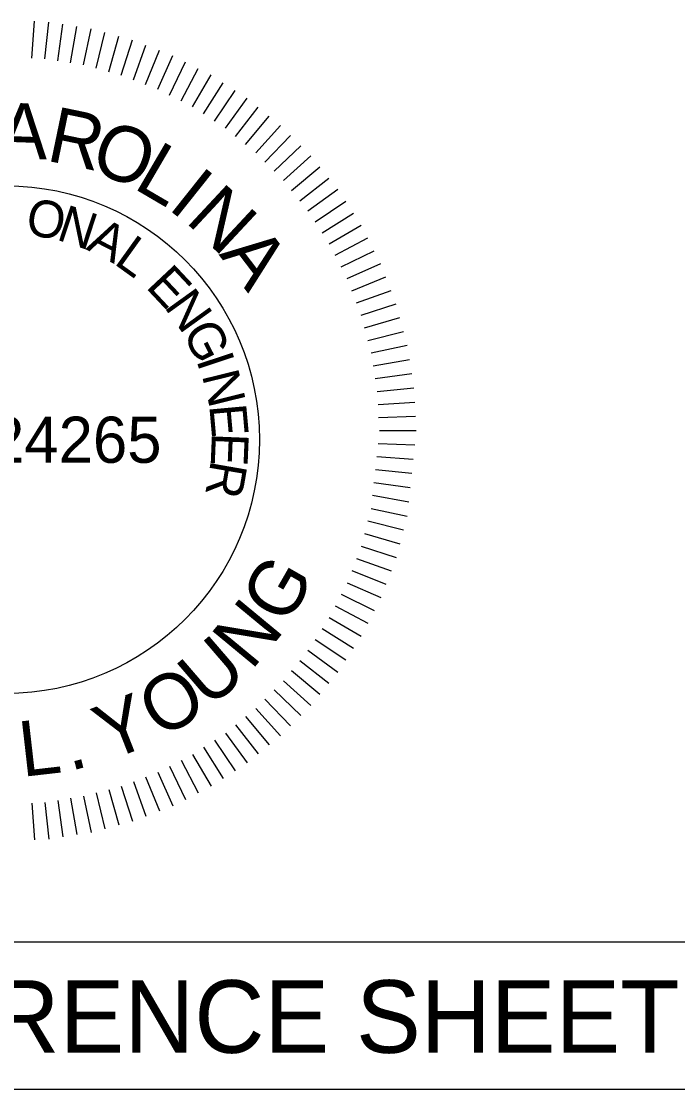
# Model space of a CAD drawing. Extents: x 1964850 to 1967424, y 1116563 to 1122204.
# Drawn here: x 1966494 to 1966557.3, y 1121679.1 to 1121782.1 of the extents above; entities that cross this region are included whole.
import ezdxf

# ---------------------------------------------------------------- set-up
doc = ezdxf.new("R2010")
doc.units = 0
doc.layers.add('RD_Sketch1', color=7, linetype='Continuous')
doc.layers.add('RD_TX_PEShield', color=7, linetype='Continuous')

msp = doc.modelspace()

# ---------------------------------------------------------------- linework, layer by layer
at = {"layer": 'RD_Sketch1'}
msp.add_lwpolyline([(1966266.73, 1121693.39), (1966567.16, 1121693.39), (1966567.16, 1121679.13), (1966266.73, 1121679.13)], close=True, dxfattribs=at)
at = {"layer": 'RD_TX_PEShield'}
for p, q in [((1966494.98, 1121778.59), (1966495.22, 1121782.14)), ((1966494.98, 1121778.59), (1966495.22, 1121782.14)), ((1966496.23, 1121778.52), (1966496.6, 1121782.06)), ((1966496.23, 1121778.52), (1966496.6, 1121782.06)), ((1966497.47, 1121778.33), (1966497.97, 1121781.85)), ((1966497.47, 1121778.33), (1966497.97, 1121781.85)), ((1966498.72, 1121778.13), (1966499.33, 1121781.63)), ((1966498.72, 1121778.13), (1966499.33, 1121781.63)), ((1966499.96, 1121777.93), (1966500.7, 1121781.41)), ((1966499.96, 1121777.93), (1966500.7, 1121781.41)), ((1966499.96, 1121777.93), (1966500.7, 1121781.41)), ((1966501.17, 1121777.61), (1966502.03, 1121781.06)), ((1966501.17, 1121777.61), (1966502.03, 1121781.06)), ((1966501.17, 1121777.61), (1966502.03, 1121781.06)), ((1966502.39, 1121777.28), (1966503.37, 1121780.7)), ((1966502.39, 1121777.28), (1966503.37, 1121780.7)), ((1966502.39, 1121777.28), (1966503.37, 1121780.7)), ((1966503.6, 1121776.96), (1966504.7, 1121780.34)), ((1966503.6, 1121776.96), (1966504.7, 1121780.34)), ((1966503.6, 1121776.96), (1966504.7, 1121780.34)), ((1966504.78, 1121776.51), (1966505.99, 1121779.85)), ((1966504.78, 1121776.51), (1966505.99, 1121779.85)), ((1966504.78, 1121776.51), (1966505.99, 1121779.85)), ((1966505.95, 1121776.05), (1966507.28, 1121779.35)), ((1966505.95, 1121776.05), (1966507.28, 1121779.35)), ((1966505.95, 1121776.05), (1966507.28, 1121779.35)), ((1966507.12, 1121775.6), (1966508.57, 1121778.86)), ((1966507.12, 1121775.6), (1966508.57, 1121778.86)), ((1966507.12, 1121775.6), (1966508.57, 1121778.86)), ((1966508.25, 1121775.03), (1966509.8, 1121778.23)), ((1966508.25, 1121775.03), (1966509.8, 1121778.23)), ((1966508.25, 1121775.03), (1966509.8, 1121778.23)), ((1966509.37, 1121774.46), (1966511.03, 1121777.6)), ((1966509.37, 1121774.46), (1966511.03, 1121777.6)), ((1966509.37, 1121774.46), (1966511.03, 1121777.6)), ((1966510.49, 1121773.89), (1966512.27, 1121776.97)), ((1966510.49, 1121773.89), (1966512.27, 1121776.97)), ((1966510.49, 1121773.89), (1966512.27, 1121776.97)), ((1966511.54, 1121773.21), (1966513.43, 1121776.22)), ((1966511.54, 1121773.21), (1966513.43, 1121776.22)), ((1966511.54, 1121773.21), (1966513.43, 1121776.22)), ((1966512.6, 1121772.52), (1966514.58, 1121775.47)), ((1966512.6, 1121772.52), (1966514.58, 1121775.47)), ((1966512.6, 1121772.52), (1966514.58, 1121775.47)), ((1966513.65, 1121771.84), (1966515.74, 1121774.72)), ((1966513.65, 1121771.84), (1966515.74, 1121774.72)), ((1966513.65, 1121771.84), (1966515.74, 1121774.72)), ((1966514.63, 1121771.04), (1966516.82, 1121773.85)), ((1966514.63, 1121771.04), (1966516.82, 1121773.85)), ((1966514.63, 1121771.04), (1966516.82, 1121773.85)), ((1966515.6, 1121770.25), (1966517.89, 1121772.98)), ((1966515.6, 1121770.25), (1966517.89, 1121772.98)), ((1966515.6, 1121770.25), (1966517.89, 1121772.98)), ((1966516.58, 1121769.46), (1966518.96, 1121772.11)), ((1966516.58, 1121769.46), (1966518.96, 1121772.11)), ((1966516.58, 1121769.46), (1966518.96, 1121772.11)), ((1966517.47, 1121768.57), (1966519.94, 1121771.13)), ((1966517.47, 1121768.57), (1966519.94, 1121771.13)), ((1966517.47, 1121768.57), (1966519.94, 1121771.13)), ((1966518.36, 1121767.68), (1966520.92, 1121770.15)), ((1966518.36, 1121767.68), (1966520.92, 1121770.15)), ((1966518.36, 1121767.68), (1966520.92, 1121770.15)), ((1966519.25, 1121766.79), (1966521.9, 1121769.18)), ((1966519.25, 1121766.79), (1966521.9, 1121769.18)), ((1966519.25, 1121766.79), (1966521.9, 1121769.18)), ((1966520.04, 1121765.82), (1966522.77, 1121768.1)), ((1966520.04, 1121765.82), (1966522.77, 1121768.1)), ((1966520.04, 1121765.82), (1966522.77, 1121768.1)), ((1966520.83, 1121764.84), (1966523.64, 1121767.03)), ((1966520.83, 1121764.84), (1966523.64, 1121767.03)), ((1966520.83, 1121764.84), (1966523.64, 1121767.03)), ((1966521.62, 1121763.86), (1966524.5, 1121765.95)), ((1966521.62, 1121763.86), (1966524.5, 1121765.95)), ((1966521.62, 1121763.86), (1966524.5, 1121765.95)), ((1966522.31, 1121762.81), (1966525.26, 1121764.79)), ((1966522.31, 1121762.81), (1966525.26, 1121764.79)), ((1966522.31, 1121762.81), (1966525.26, 1121764.79)), ((1966522.99, 1121761.75), (1966526.01, 1121763.64)), ((1966522.99, 1121761.75), (1966526.01, 1121763.64)), ((1966522.99, 1121761.75), (1966526.01, 1121763.64)), ((1966523.68, 1121760.7), (1966526.76, 1121762.48)), ((1966523.68, 1121760.7), (1966526.76, 1121762.48)), ((1966523.68, 1121760.7), (1966526.76, 1121762.48)), ((1966524.25, 1121759.58), (1966527.39, 1121761.25)), ((1966524.25, 1121759.58), (1966527.39, 1121761.25)), ((1966524.25, 1121759.58), (1966527.39, 1121761.25)), ((1966524.82, 1121758.46), (1966528.02, 1121760.02)), ((1966524.82, 1121758.46), (1966528.02, 1121760.02)), ((1966524.82, 1121758.46), (1966528.02, 1121760.02)), ((1966525.39, 1121757.34), (1966528.64, 1121758.78)), ((1966525.39, 1121757.34), (1966528.64, 1121758.78)), ((1966525.39, 1121757.34), (1966528.64, 1121758.78)), ((1966525.84, 1121756.16), (1966529.14, 1121757.49)), ((1966525.84, 1121756.16), (1966529.14, 1121757.49)), ((1966525.84, 1121756.16), (1966529.14, 1121757.49)), ((1966526.29, 1121754.99), (1966529.64, 1121756.2)), ((1966526.29, 1121754.99), (1966529.64, 1121756.2)), ((1966526.29, 1121754.99), (1966529.64, 1121756.2)), ((1966526.74, 1121753.81), (1966530.13, 1121754.91)), ((1966526.74, 1121753.81), (1966530.13, 1121754.91)), ((1966526.74, 1121753.81), (1966530.13, 1121754.91)), ((1966527.07, 1121752.6), (1966530.49, 1121753.58)), ((1966527.07, 1121752.6), (1966530.49, 1121753.58)), ((1966527.07, 1121752.6), (1966530.49, 1121753.58)), ((1966527.4, 1121751.38), (1966530.85, 1121752.24)), ((1966527.4, 1121751.38), (1966530.85, 1121752.24)), ((1966527.4, 1121751.38), (1966530.85, 1121752.24)), ((1966527.72, 1121750.17), (1966531.2, 1121750.91)), ((1966527.72, 1121750.17), (1966531.2, 1121750.91)), ((1966527.72, 1121750.17), (1966531.2, 1121750.91)), ((1966527.92, 1121748.93), (1966531.42, 1121749.54)), ((1966527.92, 1121748.93), (1966531.42, 1121749.54)), ((1966527.92, 1121748.93), (1966531.42, 1121749.54)), ((1966528.11, 1121747.69), (1966531.64, 1121748.18)), ((1966528.11, 1121747.69), (1966531.64, 1121748.18)), ((1966528.11, 1121747.69), (1966531.64, 1121748.18)), ((1966528.31, 1121746.44), (1966531.85, 1121746.81)), ((1966528.31, 1121746.44), (1966531.85, 1121746.81)), ((1966528.31, 1121746.44), (1966531.85, 1121746.81)), ((1966528.38, 1121745.19), (1966531.92, 1121745.43)), ((1966528.38, 1121745.19), (1966531.92, 1121745.43)), ((1966528.38, 1121745.19), (1966531.92, 1121745.43)), ((1966528.44, 1121743.93), (1966532, 1121744.06)), ((1966528.44, 1121743.93), (1966532, 1121744.06)), ((1966528.44, 1121743.93), (1966532, 1121744.06)), ((1966528.51, 1121742.68), (1966532.07, 1121742.68)), ((1966528.51, 1121742.68), (1966532.07, 1121742.68)), ((1966528.51, 1121742.68), (1966532.07, 1121742.68)), ((1966528.38, 1121741.42), (1966531.92, 1121741.3)), ((1966528.38, 1121741.42), (1966531.92, 1121741.3)), ((1966528.25, 1121740.17), (1966531.78, 1121739.93)), ((1966528.25, 1121740.17), (1966531.78, 1121739.93)), ((1966528.12, 1121738.93), (1966531.64, 1121738.56)), ((1966528.12, 1121738.93), (1966531.64, 1121738.56)), ((1966527.98, 1121737.68), (1966531.49, 1121737.19)), ((1966527.98, 1121737.68), (1966531.49, 1121737.19)), ((1966527.85, 1121736.44), (1966531.35, 1121735.82)), ((1966527.85, 1121736.44), (1966531.35, 1121735.82)), ((1966527.72, 1121735.18), (1966531.2, 1121734.44)), ((1966527.72, 1121735.18), (1966531.2, 1121734.44)), ((1966527.4, 1121733.97), (1966530.85, 1121733.11)), ((1966527.4, 1121733.97), (1966530.85, 1121733.11)), ((1966527.07, 1121732.75), (1966530.49, 1121731.77)), ((1966527.07, 1121732.75), (1966530.49, 1121731.77)), ((1966526.74, 1121731.54), (1966530.13, 1121730.44)), ((1966526.74, 1121731.54), (1966530.13, 1121730.44)), ((1966526.29, 1121730.36), (1966529.64, 1121729.15)), ((1966526.29, 1121730.36), (1966529.64, 1121729.15)), ((1966525.84, 1121729.19), (1966529.14, 1121727.86)), ((1966525.84, 1121729.19), (1966529.14, 1121727.86)), ((1966525.39, 1121728.01), (1966528.64, 1121726.57)), ((1966525.39, 1121728.01), (1966528.64, 1121726.57)), ((1966524.82, 1121726.89), (1966528.02, 1121725.33)), ((1966524.82, 1121726.89), (1966528.02, 1121725.33)), ((1966524.25, 1121725.77), (1966527.39, 1121724.1)), ((1966524.25, 1121725.77), (1966527.39, 1121724.1)), ((1966523.68, 1121724.65), (1966526.76, 1121722.87)), ((1966523.68, 1121724.65), (1966526.76, 1121722.87)), ((1966522.99, 1121723.6), (1966526.01, 1121721.71)), ((1966522.99, 1121723.6), (1966526.01, 1121721.71)), ((1966522.31, 1121722.54), (1966525.26, 1121720.56)), ((1966522.31, 1121722.54), (1966525.26, 1121720.56)), ((1966521.62, 1121721.49), (1966524.5, 1121719.4)), ((1966521.62, 1121721.49), (1966524.5, 1121719.4)), ((1966520.83, 1121720.51), (1966523.64, 1121718.32)), ((1966520.83, 1121720.51), (1966523.64, 1121718.32)), ((1966520.04, 1121719.53), (1966522.77, 1121717.25)), ((1966520.04, 1121719.53), (1966522.77, 1121717.25)), ((1966519.25, 1121718.56), (1966521.9, 1121716.17)), ((1966519.25, 1121718.56), (1966521.9, 1121716.17)), ((1966518.36, 1121717.67), (1966520.92, 1121715.2)), ((1966518.36, 1121717.67), (1966520.92, 1121715.2)), ((1966517.47, 1121716.78), (1966519.94, 1121714.22)), ((1966517.47, 1121716.78), (1966519.94, 1121714.22)), ((1966515.6, 1121715.1), (1966517.89, 1121712.37)), ((1966515.6, 1121715.1), (1966517.89, 1121712.37)), ((1966516.58, 1121715.89), (1966518.96, 1121713.24)), ((1966514.63, 1121714.31), (1966516.82, 1121711.5)), ((1966514.63, 1121714.31), (1966516.82, 1121711.5)), ((1966513.65, 1121713.51), (1966515.74, 1121710.63)), ((1966513.65, 1121713.51), (1966515.74, 1121710.63)), ((1966511.54, 1121712.14), (1966513.43, 1121709.13)), ((1966511.54, 1121712.14), (1966513.43, 1121709.13)), ((1966512.6, 1121712.83), (1966514.58, 1121709.88)), ((1966512.6, 1121712.83), (1966514.58, 1121709.88)), ((1966509.37, 1121710.89), (1966511.03, 1121707.75)), ((1966509.37, 1121710.89), (1966511.03, 1121707.75)), ((1966510.49, 1121711.46), (1966512.27, 1121708.38)), ((1966510.49, 1121711.46), (1966512.27, 1121708.38)), ((1966508.25, 1121710.32), (1966509.8, 1121707.12)), ((1966508.25, 1121710.32), (1966509.8, 1121707.12)), ((1966504.78, 1121708.85), (1966505.99, 1121705.5)), ((1966504.78, 1121708.85), (1966505.99, 1121705.5)), ((1966505.95, 1121709.3), (1966507.28, 1121706)), ((1966505.95, 1121709.3), (1966507.28, 1121706)), ((1966507.12, 1121709.75), (1966508.57, 1121706.49)), ((1966507.12, 1121709.75), (1966508.57, 1121706.49)), ((1966501.17, 1121707.74), (1966502.03, 1121704.29)), ((1966501.17, 1121707.74), (1966502.03, 1121704.29)), ((1966502.39, 1121708.07), (1966503.37, 1121704.65)), ((1966502.39, 1121708.07), (1966503.37, 1121704.65)), ((1966503.6, 1121708.39), (1966504.7, 1121705.01)), ((1966503.6, 1121708.39), (1966504.7, 1121705.01)), ((1966494.98, 1121706.76), (1966495.22, 1121703.21)), ((1966494.98, 1121706.76), (1966495.22, 1121703.21)), ((1966496.23, 1121706.83), (1966496.6, 1121703.29)), ((1966496.23, 1121706.83), (1966496.6, 1121703.29)), ((1966497.47, 1121707.02), (1966497.97, 1121703.5)), ((1966497.47, 1121707.02), (1966497.97, 1121703.5)), ((1966498.72, 1121707.22), (1966499.33, 1121703.72)), ((1966498.72, 1121707.22), (1966499.33, 1121703.72)), ((1966499.96, 1121707.42), (1966500.7, 1121703.94)), ((1966499.96, 1121707.42), (1966500.7, 1121703.94))]:
    msp.add_line(p, q, dxfattribs=at)
msp.add_circle((1966492.46, 1121741.8), 24.48, dxfattribs=at)

# ---------------------------------------------------------------- texts
at = {"layer": 'RD_Sketch1'}
msp.add_text('ALIGNMENT CONTROL CAN BE FOUND ON REFERENCE SHEET', height=7, dxfattribs=at).set_placement((1966270.38, 1121682.68))
at = {"layer": 'RD_TX_PEShield'}
for s, height, rotation, p in [('A', 5.34, 357.9448, (1966491.67, 1121768.99)), ('R', 5.34, 348.267, (1966496.26, 1121768.73)), ('O', 5.34, 339.3286, (1966500.39, 1121767.82)), ('L', 5.34, 329.6507, (1966504.66, 1121766.11)), ('I', 5.34, 321.4663, (1966507.99, 1121764.13)), ('N', 5.34, 317.0007, (1966509.69, 1121762.85)), ('O', 3.56, 350.4045, (1966494.26, 1121761.62)), ('N', 3.56, 341.7029, (1966497.24, 1121761.12)), ('A', 3.56, 333.0013, (1966500.11, 1121760.18)), ('L', 3.56, 324.2997, (1966502.8, 1121758.81)), ('A', 5.34, 307.3229, (1966512.98, 1121759.66)), ('E', 3.56, 313.2251, (1966505.88, 1121756.51)), ('N', 3.56, 305.7317, (1966507.68, 1121754.63)), ('G', 3.56, 297.0301, (1966509.45, 1121752.18)), ('I', 3.56, 288.3285, (1966510.82, 1121749.49)), ('N', 3.56, 283.8441, (1966511.37, 1121748.03)), ('E', 3.56, 275.1424, (1966512.09, 1121745.1)), ('E', 3.56, 267.6491, (1966512.36, 1121742.51)), ('R', 3.56, 260.1557, (1966512.28, 1121739.91)), ('G', 5.34, 60.1113, (1966519.57, 1121723.77)), ('N', 5.34, 50.4335, (1966516.16, 1121719.47)), ('U', 5.34, 40.7556, (1966512.07, 1121715.81)), ('O', 5.34, 31.0778, (1966507.42, 1121712.88)), ('Y', 5.34, 21.4, (1966502.35, 1121710.78)), ('L', 5.34, 6.5171, (1966494.05, 1121709.28)), ('.', 5.34, 14.7016, (1966498.66, 1121709.84))]:
    msp.add_text(s, height=height, rotation=rotation, dxfattribs=at).set_placement(p)
msp.add_text('NO. 24265', height=4.45, dxfattribs=at).set_placement((1966478.71, 1121739.57))

doc.saveas('drawing.dxf')
